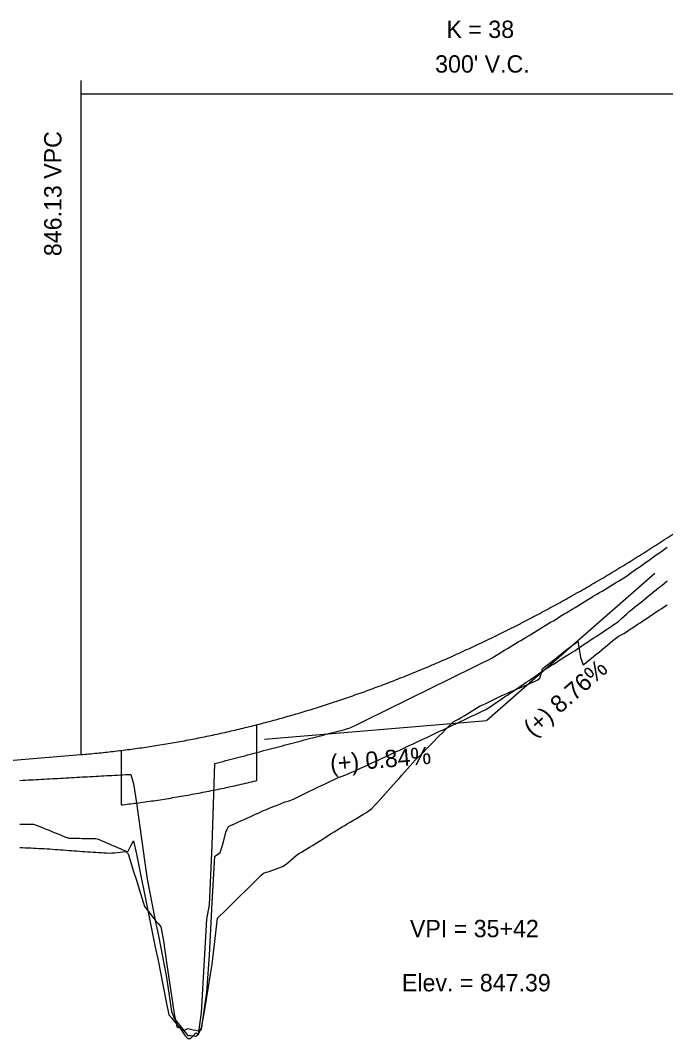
# Model space of a CAD drawing. Extents: x 1733669 to 1739080, y 1214897 to 1219897.
# Drawn here: x 1735249.5 to 1735487.8, y 1217753.2 to 1218129.3 of the extents above; entities that cross this region are included whole.
import ezdxf

# ---------------------------------------------------------------- set-up
doc = ezdxf.new("R2010")
doc.units = 0
for name, color, linetype in [('RD_DDB_GradeTX', 7, 'Continuous'), ('RD_DDB_Profile_EX', 7, 'Continuous'), ('RD_DDB_Profile_Lbl', 7, 'Continuous'), ('RD_DDB_Profile_PR', 7, 'Continuous'), ('RD_DDB_StripGrade', 7, 'Continuous'), ('RD_DDB_VCLbl', 7, 'Continuous'), ('RD_PD_Bridge', 7, 'Continuous'), ('RD_Sketch1', 7, 'Continuous'), ('RD_Sketch2', 7, 'Continuous')]:
    doc.layers.add(name, color=color, linetype=linetype)

msp = doc.modelspace()

# ---------------------------------------------------------------- linework, layer by layer
at = {"layer": 'RD_DDB_GradeTX'}
for p in [(1735483.74, 1217924.93), (1735339.66, 1217863.75)]:
    msp.add_line(p, (1735421.77, 1217870.62), dxfattribs=at)
at = {"layer": 'RD_DDB_Profile_EX'}
for points in [[(1735483.3, 1217931.09), (1735484.3, 1217931.8), (1735485.3, 1217932.51), (1735486.3, 1217933.22), (1735487.3, 1217933.93), (1735488.3, 1217934.64)], [(1735383.3, 1217873.85), (1735384.3, 1217874.35), (1735385.3, 1217874.84), (1735386.3, 1217875.33), (1735387.3, 1217875.83), (1735388.3, 1217876.32), (1735389.3, 1217876.81), (1735390.3, 1217877.31), (1735391.3, 1217877.8), (1735392.3, 1217878.3), (1735393.3, 1217878.79), (1735394.3, 1217879.28), (1735395.3, 1217879.78), (1735396.3, 1217880.28), (1735397.3, 1217880.77), (1735398.3, 1217881.26), (1735399.3, 1217881.76), (1735400.3, 1217882.25), (1735401.3, 1217882.74), (1735402.3, 1217883.23), (1735403.3, 1217883.73), (1735404.3, 1217884.22), (1735405.3, 1217884.71), (1735406.3, 1217885.21), (1735407.3, 1217885.7), (1735408.3, 1217886.19), (1735409.3, 1217886.68), (1735410.3, 1217887.18), (1735411.3, 1217887.67), (1735412.3, 1217888.16), (1735413.3, 1217888.65), (1735414.3, 1217889.15), (1735415.3, 1217889.64), (1735416.3, 1217890.13), (1735417.3, 1217890.62), (1735418.3, 1217891.12), (1735419.3, 1217891.61), (1735420.3, 1217892.1), (1735421.3, 1217892.59), (1735422.3, 1217893.09), (1735423.3, 1217893.62), (1735424.3, 1217894.23), (1735425.3, 1217894.83), (1735426.3, 1217895.44), (1735427.3, 1217896.04), (1735428.3, 1217896.65), (1735429.3, 1217897.25), (1735430.3, 1217897.86), (1735431.3, 1217898.46), (1735432.3, 1217899.06), (1735433.3, 1217899.67), (1735434.3, 1217900.27), (1735435.3, 1217900.88), (1735436.3, 1217901.48), (1735437.3, 1217902.09), (1735438.3, 1217902.69), (1735439.3, 1217903.29), (1735440.3, 1217903.9), (1735441.3, 1217904.5), (1735442.3, 1217905.11), (1735443.3, 1217905.71), (1735444.3, 1217906.31), (1735445.3, 1217906.92), (1735446.3, 1217907.52), (1735447.3, 1217908.13), (1735448.3, 1217908.78), (1735449.3, 1217909.4), (1735450.3, 1217910.01), (1735451.3, 1217910.61), (1735452.3, 1217911.22), (1735453.3, 1217911.82), (1735454.3, 1217912.43), (1735455.3, 1217913.03), (1735456.3, 1217913.64), (1735457.3, 1217914.25), (1735458.3, 1217914.85), (1735459.3, 1217915.46), (1735460.3, 1217916.06), (1735461.3, 1217916.67), (1735462.3, 1217917.27), (1735463.3, 1217917.88), (1735464.3, 1217918.48), (1735465.3, 1217919.09), (1735466.3, 1217919.7), (1735467.3, 1217920.3), (1735468.3, 1217920.91), (1735469.3, 1217921.51), (1735470.3, 1217922.12), (1735471.3, 1217922.72), (1735472.3, 1217923.33), (1735473.3, 1217924.01), (1735474.3, 1217924.71), (1735475.3, 1217925.42), (1735476.3, 1217926.13), (1735477.3, 1217926.84), (1735478.3, 1217927.55), (1735479.3, 1217928.26), (1735480.3, 1217928.97), (1735481.3, 1217929.67), (1735482.3, 1217930.38), (1735483.3, 1217931.09)], [(1735283.3, 1217850.4), (1735284.3, 1217850.45), (1735285.3, 1217850.5), (1735286.3, 1217850.56), (1735287.3, 1217850.61), (1735288.3, 1217850.66), (1735289.3, 1217850.72), (1735290.3, 1217850.77), (1735291.3, 1217847.31), (1735292.3, 1217840.23), (1735293.3, 1217833.15), (1735294.3, 1217826.07), (1735295.3, 1217818.99), (1735296.3, 1217812.1), (1735297.3, 1217807.01), (1735298.3, 1217801.92), (1735299.3, 1217796.83), (1735300.3, 1217791.74), (1735301.3, 1217786.65), (1735302.3, 1217781.56), (1735303.3, 1217776.47), (1735304.3, 1217769.97), (1735305.3, 1217763.15), (1735306.3, 1217760.74), (1735307.3, 1217759.31), (1735308.3, 1217758.07), (1735309.3, 1217756.82), (1735310.3, 1217755.57), (1735311.3, 1217754.33), (1735312.3, 1217754.27), (1735313.3, 1217754.2), (1735314.3, 1217754.13), (1735315.3, 1217754.86), (1735316.3, 1217762.82), (1735317.3, 1217780.05), (1735318.3, 1217797.27), (1735319.3, 1217802.6), (1735320.3, 1217824.53), (1735321.3, 1217854.77), (1735322.3, 1217855.03), (1735323.3, 1217855.3), (1735324.3, 1217855.56), (1735325.3, 1217855.83), (1735326.3, 1217856.09), (1735327.3, 1217856.35), (1735328.3, 1217856.62), (1735329.3, 1217856.88), (1735330.3, 1217857.15), (1735331.3, 1217857.41), (1735332.3, 1217857.67), (1735333.3, 1217857.94), (1735334.3, 1217858.2), (1735335.3, 1217858.46), (1735336.3, 1217858.73), (1735337.3, 1217858.99), (1735338.3, 1217859.26), (1735339.3, 1217859.52), (1735340.3, 1217859.78), (1735341.3, 1217860.05), (1735342.3, 1217860.31), (1735343.3, 1217860.57), (1735344.3, 1217860.84), (1735345.3, 1217861.09), (1735346.3, 1217861.36), (1735347.3, 1217861.62), (1735348.3, 1217861.88), (1735349.3, 1217862.15), (1735350.3, 1217862.41), (1735351.3, 1217862.67), (1735352.3, 1217862.93), (1735353.3, 1217863.2), (1735354.3, 1217863.46), (1735355.3, 1217863.72), (1735356.3, 1217863.98), (1735357.3, 1217864.25), (1735358.3, 1217864.51), (1735359.3, 1217864.77), (1735360.3, 1217865.03), (1735361.3, 1217865.3), (1735362.3, 1217865.56), (1735363.3, 1217865.82), (1735364.3, 1217866.08), (1735365.3, 1217866.35), (1735366.3, 1217866.61), (1735367.3, 1217866.87), (1735368.3, 1217867.13), (1735369.3, 1217867.39), (1735370.3, 1217867.65), (1735371.3, 1217867.92), (1735372.3, 1217868.42), (1735373.3, 1217868.91), (1735374.3, 1217869.4), (1735375.3, 1217869.9), (1735376.3, 1217870.39), (1735377.3, 1217870.89), (1735378.3, 1217871.38), (1735379.3, 1217871.88), (1735380.3, 1217872.37), (1735381.3, 1217872.86), (1735382.3, 1217873.36), (1735383.3, 1217873.85)], [(1735249.3, 1217848.53), (1735250.3, 1217848.58), (1735251.3, 1217848.64), (1735252.3, 1217848.69), (1735253.3, 1217848.75), (1735254.3, 1217848.8), (1735255.3, 1217848.86), (1735256.3, 1217848.91), (1735257.3, 1217848.97), (1735258.3, 1217849.02), (1735259.3, 1217849.08), (1735260.3, 1217849.13), (1735261.3, 1217849.19), (1735262.3, 1217849.24), (1735263.3, 1217849.3), (1735264.3, 1217849.35), (1735265.3, 1217849.41), (1735266.3, 1217849.48), (1735267.3, 1217849.54), (1735268.3, 1217849.59), (1735269.3, 1217849.64), (1735270.3, 1217849.7), (1735271.3, 1217849.75), (1735272.3, 1217849.81), (1735273.3, 1217849.86), (1735274.3, 1217849.91), (1735275.3, 1217849.97), (1735276.3, 1217850.02), (1735277.3, 1217850.08), (1735278.3, 1217850.13), (1735279.3, 1217850.18), (1735280.3, 1217850.24), (1735281.3, 1217850.29), (1735282.3, 1217850.34), (1735283.3, 1217850.4)]]:
    msp.add_lwpolyline(points, dxfattribs=at)
at = {"layer": 'RD_DDB_Profile_PR'}
msp.add_line((1735240.77, 1217855.48), (1735271.77, 1217858.07), dxfattribs=at)
msp.add_spline([(1735271.77, 1217858.07), (1735277.77, 1217858.62), (1735283.77, 1217859.27), (1735289.77, 1217860.01), (1735295.77, 1217860.84), (1735301.77, 1217861.77), (1735307.77, 1217862.8), (1735313.77, 1217863.92), (1735319.77, 1217865.13), (1735325.77, 1217866.44), (1735331.77, 1217867.85), (1735337.77, 1217869.35), (1735343.77, 1217870.95), (1735349.77, 1217872.64), (1735355.77, 1217874.42), (1735361.77, 1217876.3), (1735367.77, 1217878.28), (1735373.77, 1217880.35), (1735379.77, 1217882.52), (1735385.77, 1217884.78), (1735391.77, 1217887.14), (1735397.77, 1217889.59), (1735403.77, 1217892.14), (1735409.77, 1217894.78), (1735415.77, 1217897.52), (1735421.77, 1217900.35), (1735427.77, 1217903.28), (1735433.77, 1217906.3), (1735439.77, 1217909.42), (1735445.77, 1217912.63), (1735451.77, 1217915.94), (1735457.77, 1217919.34), (1735463.77, 1217922.84), (1735469.77, 1217926.43), (1735475.77, 1217930.12), (1735481.77, 1217933.91), (1735487.77, 1217937.78), (1735493.77, 1217941.76), (1735499.77, 1217945.83), (1735505.77, 1217949.99), (1735511.77, 1217954.25), (1735517.77, 1217958.6), (1735523.77, 1217963.05), (1735529.77, 1217967.6), (1735535.77, 1217972.24), (1735541.77, 1217976.97), (1735547.77, 1217981.8), (1735553.77, 1217986.73), (1735559.77, 1217991.75), (1735565.77, 1217996.86), (1735571.77, 1218002.08)], degree=3, dxfattribs=at)
at = {"layer": 'RD_DDB_VCLbl'}
for p, q in [((1735271.77, 1218107.08), (1735271.77, 1217858.07)), ((1735271.77, 1218102.08), (1735571.77, 1218102.08))]:
    msp.add_line(p, q, dxfattribs=at)
at = {"layer": 'RD_PD_Bridge'}
for p, q in [((1735336.77, 1217848.48), (1735336.77, 1217869.09)), ((1735286.77, 1217839.48), (1735286.77, 1217859.63))]:
    msp.add_line(p, q, dxfattribs=at)
msp.add_spline([(1735286.77, 1217839.48), (1735292.37, 1217840.18), (1735298.68, 1217841.05), (1735304.99, 1217842.03), (1735311.29, 1217843.11), (1735317.59, 1217844.29), (1735323.89, 1217845.56), (1735330.19, 1217846.94), (1735336.48, 1217848.41), (1735336.77, 1217848.48)], degree=3, dxfattribs=at)
at = {"layer": 'RD_Sketch1'}
for points in [[(1735483.3, 1217910.08), (1735484.3, 1217910.74), (1735485.3, 1217911.4), (1735486.3, 1217912.07), (1735487.3, 1217912.73), (1735488.3, 1217913.39)], [(1735383.3, 1217842.62), (1735384.3, 1217843.73), (1735385.3, 1217844.85), (1735386.3, 1217845.96), (1735387.3, 1217847.07), (1735388.3, 1217848.19), (1735389.3, 1217849.3), (1735390.3, 1217850.42), (1735391.3, 1217851.54), (1735392.3, 1217852.65), (1735393.3, 1217853.77), (1735394.3, 1217854.88), (1735395.3, 1217855.95), (1735396.3, 1217856.97), (1735397.3, 1217857.99), (1735398.3, 1217859), (1735399.3, 1217860.02), (1735400.3, 1217861.04), (1735401.3, 1217862.06), (1735402.3, 1217863.08), (1735403.3, 1217864.1), (1735404.3, 1217865.12), (1735405.3, 1217866.14), (1735406.3, 1217867.16), (1735407.3, 1217868.18), (1735408.3, 1217869.2), (1735409.3, 1217870.18), (1735410.3, 1217870.64), (1735411.3, 1217871.14), (1735412.3, 1217871.76), (1735413.3, 1217872.38), (1735414.3, 1217872.99), (1735415.3, 1217873.61), (1735416.3, 1217874.22), (1735417.3, 1217874.84), (1735418.3, 1217875.45), (1735419.3, 1217876.02), (1735420.3, 1217876.5), (1735421.3, 1217876.97), (1735422.3, 1217877.45), (1735423.3, 1217877.93), (1735424.3, 1217878.4), (1735425.3, 1217878.88), (1735426.3, 1217879.36), (1735427.3, 1217879.84), (1735428.3, 1217880.31), (1735429.3, 1217880.79), (1735430.3, 1217881.21), (1735431.3, 1217881.63), (1735432.3, 1217882.04), (1735433.3, 1217882.46), (1735434.3, 1217882.88), (1735435.3, 1217883.3), (1735436.3, 1217883.72), (1735437.3, 1217884.18), (1735438.3, 1217884.64), (1735439.3, 1217885.09), (1735440.3, 1217885.53), (1735441.3, 1217886.3), (1735442.3, 1217889.76), (1735443.3, 1217890.55), (1735444.3, 1217891.34), (1735445.3, 1217892.14), (1735446.3, 1217892.93), (1735447.3, 1217893.72), (1735448.3, 1217894.51), (1735449.3, 1217895.31), (1735450.3, 1217896.1), (1735451.3, 1217896.86), (1735452.3, 1217897.62), (1735453.3, 1217898.38), (1735454.3, 1217899.15), (1735455.3, 1217899.91), (1735456.3, 1217893.87), (1735457.3, 1217891.16), (1735458.3, 1217891.98), (1735459.3, 1217892.79), (1735460.3, 1217893.61), (1735461.3, 1217894.43), (1735462.3, 1217895.25), (1735463.3, 1217896.07), (1735464.3, 1217896.89), (1735465.3, 1217897.72), (1735466.3, 1217898.54), (1735467.3, 1217899.36), (1735468.3, 1217900.18), (1735469.3, 1217901), (1735470.3, 1217901.75), (1735471.3, 1217902.27), (1735472.3, 1217902.79), (1735473.3, 1217903.44), (1735474.3, 1217904.1), (1735475.3, 1217904.76), (1735476.3, 1217905.43), (1735477.3, 1217906.09), (1735478.3, 1217906.76), (1735479.3, 1217907.42), (1735480.3, 1217908.08), (1735481.3, 1217908.75), (1735482.3, 1217909.41), (1735483.3, 1217910.08)], [(1735283.3, 1217824.67), (1735284.3, 1217824.24), (1735285.3, 1217823.81), (1735286.3, 1217823.38), (1735287.3, 1217822.95), (1735288.3, 1217822.52), (1735289.3, 1217821.41), (1735290.3, 1217818.16), (1735291.3, 1217814.91), (1735292.3, 1217811.66), (1735293.3, 1217808.4), (1735294.3, 1217805.15), (1735295.3, 1217801.93), (1735296.3, 1217800.68), (1735297.3, 1217799.44), (1735298.3, 1217798.19), (1735299.3, 1217796.94), (1735300.3, 1217795.69), (1735301.3, 1217794.44), (1735302.3, 1217789.25), (1735303.3, 1217782.14), (1735304.3, 1217775.53), (1735305.3, 1217768.92), (1735306.3, 1217762.3), (1735307.3, 1217757.52), (1735308.3, 1217757.14), (1735309.3, 1217755.65), (1735310.3, 1217754.16), (1735311.3, 1217753.26), (1735312.3, 1217753.16), (1735313.3, 1217754.14), (1735314.3, 1217755.29), (1735315.3, 1217754.8), (1735316.3, 1217757.24), (1735317.3, 1217762.47), (1735318.3, 1217768.5), (1735319.3, 1217774.59), (1735320.3, 1217780.67), (1735321.3, 1217789.02), (1735322.3, 1217797.68), (1735323.3, 1217798.67), (1735324.3, 1217799.65), (1735325.3, 1217800.64), (1735326.3, 1217801.63), (1735327.3, 1217802.61), (1735328.3, 1217803.6), (1735329.3, 1217804.58), (1735330.3, 1217805.56), (1735331.3, 1217806.54), (1735332.3, 1217807.52), (1735333.3, 1217808.5), (1735334.3, 1217809.47), (1735335.3, 1217810.45), (1735336.3, 1217811.42), (1735337.3, 1217812.4), (1735338.3, 1217813.37), (1735339.3, 1217814.23), (1735340.3, 1217814.59), (1735341.3, 1217814.95), (1735342.3, 1217815.31), (1735343.3, 1217815.66), (1735344.3, 1217816.02), (1735345.3, 1217816.37), (1735346.3, 1217816.73), (1735347.3, 1217817.31), (1735348.3, 1217818.18), (1735349.3, 1217819.05), (1735350.3, 1217819.92), (1735351.3, 1217820.79), (1735352.3, 1217821.57), (1735353.3, 1217822.03), (1735354.3, 1217822.66), (1735355.3, 1217823.28), (1735356.3, 1217823.9), (1735357.3, 1217824.53), (1735358.3, 1217825.15), (1735359.3, 1217825.77), (1735360.3, 1217826.39), (1735361.3, 1217827.01), (1735362.3, 1217827.63), (1735363.3, 1217828.25), (1735364.3, 1217828.87), (1735365.3, 1217829.48), (1735366.3, 1217830.1), (1735367.3, 1217830.72), (1735368.3, 1217831.33), (1735369.3, 1217831.94), (1735370.3, 1217832.56), (1735371.3, 1217833.17), (1735372.3, 1217833.78), (1735373.3, 1217834.39), (1735374.3, 1217835), (1735375.3, 1217835.6), (1735376.3, 1217836.21), (1735377.3, 1217836.74), (1735378.3, 1217837.39), (1735379.3, 1217838.16), (1735380.3, 1217839.28), (1735381.3, 1217840.39), (1735382.3, 1217841.5), (1735383.3, 1217842.62)], [(1735249.3, 1217832.38), (1735250.3, 1217832.39), (1735251.3, 1217832.39), (1735252.3, 1217832.4), (1735253.3, 1217832.41), (1735254.3, 1217832.41), (1735255.3, 1217832.03), (1735256.3, 1217831.62), (1735257.3, 1217831.22), (1735258.3, 1217830.82), (1735259.3, 1217830.41), (1735260.3, 1217830.01), (1735261.3, 1217829.6), (1735262.3, 1217829.2), (1735263.3, 1217828.79), (1735264.3, 1217828.39), (1735265.3, 1217827.98), (1735266.3, 1217827.57), (1735267.3, 1217827.19), (1735268.3, 1217827.18), (1735269.3, 1217827.17), (1735270.3, 1217827.16), (1735271.3, 1217827.14), (1735272.3, 1217827.13), (1735273.3, 1217827.12), (1735274.3, 1217827.1), (1735275.3, 1217827.09), (1735276.3, 1217827.08), (1735277.3, 1217827.06), (1735278.3, 1217826.82), (1735279.3, 1217826.39), (1735280.3, 1217825.96), (1735281.3, 1217825.53), (1735282.3, 1217825.1), (1735283.3, 1217824.67)]]:
    msp.add_lwpolyline(points, dxfattribs=at)
at = {"layer": 'RD_Sketch2'}
for points in [[(1735483.3, 1217918.15), (1735484.3, 1217918.96), (1735485.3, 1217919.77), (1735486.3, 1217920.58), (1735487.3, 1217921.39), (1735488.3, 1217922.2)], [(1735383.3, 1217856.83), (1735384.3, 1217857.3), (1735385.3, 1217857.76), (1735386.3, 1217858.23), (1735387.3, 1217858.69), (1735388.3, 1217859.16), (1735389.3, 1217859.62), (1735390.3, 1217860.09), (1735391.3, 1217860.55), (1735392.3, 1217861.03), (1735393.3, 1217861.5), (1735394.3, 1217861.98), (1735395.3, 1217862.45), (1735396.3, 1217862.92), (1735397.3, 1217863.39), (1735398.3, 1217863.86), (1735399.3, 1217864.32), (1735400.3, 1217864.79), (1735401.3, 1217865.26), (1735402.3, 1217865.73), (1735403.3, 1217866.2), (1735404.3, 1217866.67), (1735405.3, 1217867.14), (1735406.3, 1217867.61), (1735407.3, 1217868.08), (1735408.3, 1217868.55), (1735409.3, 1217869.02), (1735410.3, 1217869.49), (1735411.3, 1217869.97), (1735412.3, 1217870.44), (1735413.3, 1217870.91), (1735414.3, 1217871.38), (1735415.3, 1217871.86), (1735416.3, 1217872.33), (1735417.3, 1217872.8), (1735418.3, 1217873.28), (1735419.3, 1217873.76), (1735420.3, 1217874.24), (1735421.3, 1217874.71), (1735422.3, 1217875.33), (1735423.3, 1217876), (1735424.3, 1217876.68), (1735425.3, 1217877.35), (1735426.3, 1217878.03), (1735427.3, 1217878.71), (1735428.3, 1217879.38), (1735429.3, 1217880.06), (1735430.3, 1217880.74), (1735431.3, 1217881.41), (1735432.3, 1217882.09), (1735433.3, 1217882.77), (1735434.3, 1217883.45), (1735435.3, 1217884.13), (1735436.3, 1217884.81), (1735437.3, 1217885.49), (1735438.3, 1217886.17), (1735439.3, 1217886.85), (1735440.3, 1217887.53), (1735441.3, 1217888.21), (1735442.3, 1217888.94), (1735443.3, 1217889.68), (1735444.3, 1217890.28), (1735445.3, 1217890.88), (1735446.3, 1217891.49), (1735447.3, 1217892.14), (1735448.3, 1217892.82), (1735449.3, 1217893.45), (1735450.3, 1217894.05), (1735451.3, 1217894.66), (1735452.3, 1217895.26), (1735453.3, 1217895.91), (1735454.3, 1217896.57), (1735455.3, 1217897.24), (1735456.3, 1217897.9), (1735457.3, 1217898.56), (1735458.3, 1217899.22), (1735459.3, 1217899.88), (1735460.3, 1217900.55), (1735461.3, 1217901.21), (1735462.3, 1217901.87), (1735463.3, 1217902.53), (1735464.3, 1217903.19), (1735465.3, 1217903.85), (1735466.3, 1217904.51), (1735467.3, 1217905.17), (1735468.3, 1217905.83), (1735469.3, 1217906.49), (1735470.3, 1217907.26), (1735471.3, 1217908.17), (1735472.3, 1217909.08), (1735473.3, 1217909.99), (1735474.3, 1217910.86), (1735475.3, 1217911.67), (1735476.3, 1217912.48), (1735477.3, 1217913.29), (1735478.3, 1217914.1), (1735479.3, 1217914.91), (1735480.3, 1217915.72), (1735481.3, 1217916.53), (1735482.3, 1217917.34), (1735483.3, 1217918.15)], [(1735283.3, 1217821.73), (1735284.3, 1217821.83), (1735285.3, 1217821.94), (1735286.3, 1217822.05), (1735287.3, 1217822.16), (1735288.3, 1217822.27), (1735289.3, 1217822.45), (1735290.3, 1217824.38), (1735291.3, 1217826.22), (1735292.3, 1217821.31), (1735293.3, 1217816.4), (1735294.3, 1217811.49), (1735295.3, 1217806.58), (1735296.3, 1217801.67), (1735297.3, 1217796.76), (1735298.3, 1217791.85), (1735299.3, 1217786.94), (1735300.3, 1217782.03), (1735301.3, 1217776.96), (1735302.3, 1217771.83), (1735303.3, 1217766.71), (1735304.3, 1217762), (1735305.3, 1217760.8), (1735306.3, 1217759.6), (1735307.3, 1217758.41), (1735308.3, 1217757.21), (1735309.3, 1217756.02), (1735310.3, 1217756.46), (1735311.3, 1217756.91), (1735312.3, 1217756.6), (1735313.3, 1217756.41), (1735314.3, 1217756.23), (1735315.3, 1217756.04), (1735316.3, 1217756.52), (1735317.3, 1217763.44), (1735318.3, 1217770.37), (1735319.3, 1217783.95), (1735320.3, 1217803.3), (1735321.3, 1217820.56), (1735322.3, 1217821.22), (1735323.3, 1217821.87), (1735324.3, 1217825.37), (1735325.3, 1217829.38), (1735326.3, 1217831.52), (1735327.3, 1217831.97), (1735328.3, 1217832.42), (1735329.3, 1217832.87), (1735330.3, 1217833.32), (1735331.3, 1217833.77), (1735332.3, 1217834.22), (1735333.3, 1217834.68), (1735334.3, 1217835.13), (1735335.3, 1217835.58), (1735336.3, 1217836.03), (1735337.3, 1217836.49), (1735338.3, 1217836.94), (1735339.3, 1217837.4), (1735340.3, 1217837.85), (1735341.3, 1217838.31), (1735342.3, 1217838.71), (1735343.3, 1217839.08), (1735344.3, 1217839.45), (1735345.3, 1217839.82), (1735346.3, 1217840.19), (1735347.3, 1217840.56), (1735348.3, 1217840.92), (1735349.3, 1217841.29), (1735350.3, 1217841.66), (1735351.3, 1217842.12), (1735352.3, 1217842.6), (1735353.3, 1217843.08), (1735354.3, 1217843.57), (1735355.3, 1217844.05), (1735356.3, 1217844.54), (1735357.3, 1217845.02), (1735358.3, 1217845.51), (1735359.3, 1217845.99), (1735360.3, 1217846.48), (1735361.3, 1217846.96), (1735362.3, 1217847.45), (1735363.3, 1217847.94), (1735364.3, 1217848.42), (1735365.3, 1217848.91), (1735366.3, 1217849.39), (1735367.3, 1217849.76), (1735368.3, 1217850.12), (1735369.3, 1217850.49), (1735370.3, 1217850.85), (1735371.3, 1217851.29), (1735372.3, 1217851.75), (1735373.3, 1217852.21), (1735374.3, 1217852.67), (1735375.3, 1217853.13), (1735376.3, 1217853.59), (1735377.3, 1217854.06), (1735378.3, 1217854.52), (1735379.3, 1217854.98), (1735380.3, 1217855.44), (1735381.3, 1217855.91), (1735382.3, 1217856.37), (1735383.3, 1217856.83)], [(1735249.3, 1217823.8), (1735250.3, 1217823.73), (1735251.3, 1217823.67), (1735252.3, 1217823.62), (1735253.3, 1217823.58), (1735254.3, 1217823.53), (1735255.3, 1217823.49), (1735256.3, 1217823.44), (1735257.3, 1217823.4), (1735258.3, 1217823.35), (1735259.3, 1217823.29), (1735260.3, 1217823.21), (1735261.3, 1217823.14), (1735262.3, 1217823.06), (1735263.3, 1217822.99), (1735264.3, 1217822.91), (1735265.3, 1217822.84), (1735266.3, 1217822.76), (1735267.3, 1217822.69), (1735268.3, 1217822.62), (1735269.3, 1217822.55), (1735270.3, 1217822.48), (1735271.3, 1217822.4), (1735272.3, 1217822.33), (1735273.3, 1217822.26), (1735274.3, 1217822.19), (1735275.3, 1217822.13), (1735276.3, 1217822.06), (1735277.3, 1217821.99), (1735278.3, 1217821.92), (1735279.3, 1217821.85), (1735280.3, 1217821.79), (1735281.3, 1217821.74), (1735282.3, 1217821.66), (1735283.3, 1217821.73)]]:
    msp.add_lwpolyline(points, dxfattribs=at)

# ---------------------------------------------------------------- texts
at = {"layer": 'RD_DDB_GradeTX'}
for s, rotation, p in [('(+) 8.76%', 41.2297, (1735438.8, 1217864.34)), ('(+) 0.84%', 4.7825, (1735364.13, 1217851.57))]:
    msp.add_text(s, height=6.4, rotation=rotation, dxfattribs=at).set_placement(p)
at = {"layer": 'RD_DDB_Profile_Lbl'}
for s, p in [('VPI = 35+42', (1735393.33, 1217790.62)), ('Elev. = 847.39', (1735390.37, 1217770.62))]:
    msp.add_text(s, height=6.4, dxfattribs=at).set_placement(p)
at = {"layer": 'RD_DDB_StripGrade'}
msp.add_text('846.13 VPC', height=6.4, rotation=90, dxfattribs=at).set_placement((1735264.65, 1218042.18))
at = {"layer": 'RD_DDB_VCLbl'}
for s, p in [('K = 38', (1735406.81, 1218122.76)), ("300' V.C.", (1735402.64, 1218109.96))]:
    msp.add_text(s, height=6.4, dxfattribs=at).set_placement(p)

doc.saveas('drawing.dxf')
